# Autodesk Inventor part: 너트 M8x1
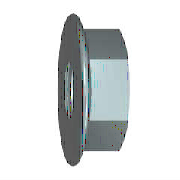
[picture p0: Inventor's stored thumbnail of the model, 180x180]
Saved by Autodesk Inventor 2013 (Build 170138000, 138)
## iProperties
Created: 2015-12
Part Number: 너트 M8x1
Material: 스테인리스강
Description: 플랜지붙이 6각 너트 - 일반 스레드
Document SubType Name: Modeling
Standard: ISO 4161
Designer: mdu
Standard Revision: 2판 1999-03-15
Standards Organization: ISO
Language: ko-KR
Size Designation: M8
Categories: <MemberInstance><Categories><Category DisplayName="조임쇠" InternalName="e4da775c-781d-43d5-af7c-5136215cf5a6" Mnemonic="FSTN"><Category DisplayName="너트" InternalN
Density: 8.08 g/cm^3
Author: mdu
IsCustomPart: 1
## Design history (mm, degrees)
sketch "스케치1"
  geometry: L1 (-1.844, 0)-(9.641, 0) reference; L2 (3.107, 6.5)-(2.288, 8.257); L3 (3.107, 6.5)-(8, 6.5); L4 (8, 6.5)-(8, 0); L5 (3.107, 6.5)-(3.107, 0); L6 (0, -1.835)-(0, 11.01) reference; A1 r 1.2 centre (1.2, 7.75) between (2.288, 8.257) and (0, 7.75); 1 further point
  constraints: 8 end point, 3 point on line, 2 perpendicular, 2 point on circle, 2 tangent, 1 centre point, 1 parallel
  dimensions: "d2" = 13 diameter of L3 L1 (= SW); "d4" = 17.9 dimension on A1 L1 (= LADI); "d5" = 1.2 radius of A1 (= PHH); "d15" = 8 distance between parallel lines of L4 L6 (= KOH); "d16" = 25 deg angle of L6 L2 (= KEWI)
revolve "링" sketch "스케치1" stored, may be unused: angle "d8" = 90 deg
sketch "스케치2"
  geometry: L1 (-6.5, -3.753)-(-6.5, 3.753); L2 (-6.5, 3.753)-(0, 7.506); L3 (0, 7.506)-(6.5, 3.753); L4 (6.5, 3.753)-(6.5, -3.753); L5 (6.5, -3.753)-(0, -7.506); L6 (0, -7.506)-(-6.5, -3.753); C1 r 4.9 at (0, 0); C2 r 7.75 at (0, 0) reference; 1 further point
  constraints: 12 end point, 1 centre point, 1 coincident, 1 vertical, 11 other
  dimensions: "d6" = 15.01111 distance of L5.end L2.end (= 1.1547 x SW)
extrude "본체" join sketch "스케치2" distance "d7" = 8 (= KOH); taper "d9" = 0 deg
sketch "스케치3"
  geometry: L1 (2.638, 7.506)-(8, 7.506) reference; L2 (8, 3.753)-(8, 7.506) reference; L3 (0, -7.75)-(0, 7.75) reference; L4 (-1.6, 0)-(9.6, 0) reference; L5 (7.419, 7.506)-(8, 6.5)
  constraints: 2 end point, 2 point on line
  dimensions: "d10" = 30 deg angle of L2 L5 (= ANG1); "d11" = 13 diameter of L5.end L4 (= SW0)
revolve "모따기1" sketch "스케치3" stored, may be unused: angle "d24" = 90 deg
sketch "스케치4"
  geometry: C1 r 7.75 at (0, 0) reference; 1 further point
  constraints: 1 coincident
hole "스레드" sketch "스케치4" at (0, 0) diameter "d25" = 6.647; stored, may be unused: countersink angle "d29" = 82 deg, drill point angle "d31" = 118 deg; dims "d26" = 6, "d27" = 4, "d28" = 2, "d30" = 8
workaxis "Work Axis1"
workplane "Work Plane1"
body "Solid1"
chamfer "모따기2" distance "d12" = 0.67658 (= -0.5 x GD1 + 0.5 x NND); stored, may be unused: angle "d13" = 30 deg, second distance "d46" = 0.67658 (= -0.5 x GD1 + 0.5 x NND)
chamfer "모따기3" distance "d51" = 0.67658 (= -0.5 x GD1 + 0.5 x NND); stored, may be unused: second distance "d52" = 2, angle "d53" = 45 deg
other parameters: "ANG1" = 30 deg [user parameter; used in 1 equation term], "KEWI" = 25 deg [user parameter; used in 1 equation term], "NND" = 8 [user parameter; used in 4 equation terms], "LADI" = 17.9 [user parameter; used in 2 equation terms], "SW" = 13 [user parameter; used in 3 equation terms], "PHH" = 1.2 [user parameter; used in 3 equation terms], "KOH" = 8 (= NND) [user parameter; used in 2 equation terms], "SW0" = 13 [user parameter; used in 1 equation term], "GD1" = 6.64684 (computed from THREADDIA, PTC, TOA) [user parameter; used in 3 equation terms], "d1" = 17.9 (= LADI), "d3" = 1.2 (= PHH), "d45" = 0, "d47" = 0, "d49" = 0, "d54" = 0, "GUL" = 0.67658 (= 0.541266 x PTC) [user parameter], "TPU" = 8 (computed from PTC) [user parameter], "RR" = 1.2 (= PHH) [user parameter], "THREADDIA" = 8 [user parameter; used in 1 equation term], "TOA" = 30 deg [user parameter; used in 1 equation term], "PTC" = 1.25 [user parameter; used in 4 equation terms], "GAL" = 0.67658 (= 0.541266 x PTC) [user parameter], "E0" = 15.015 (= 1.155 x SW) [user parameter]
